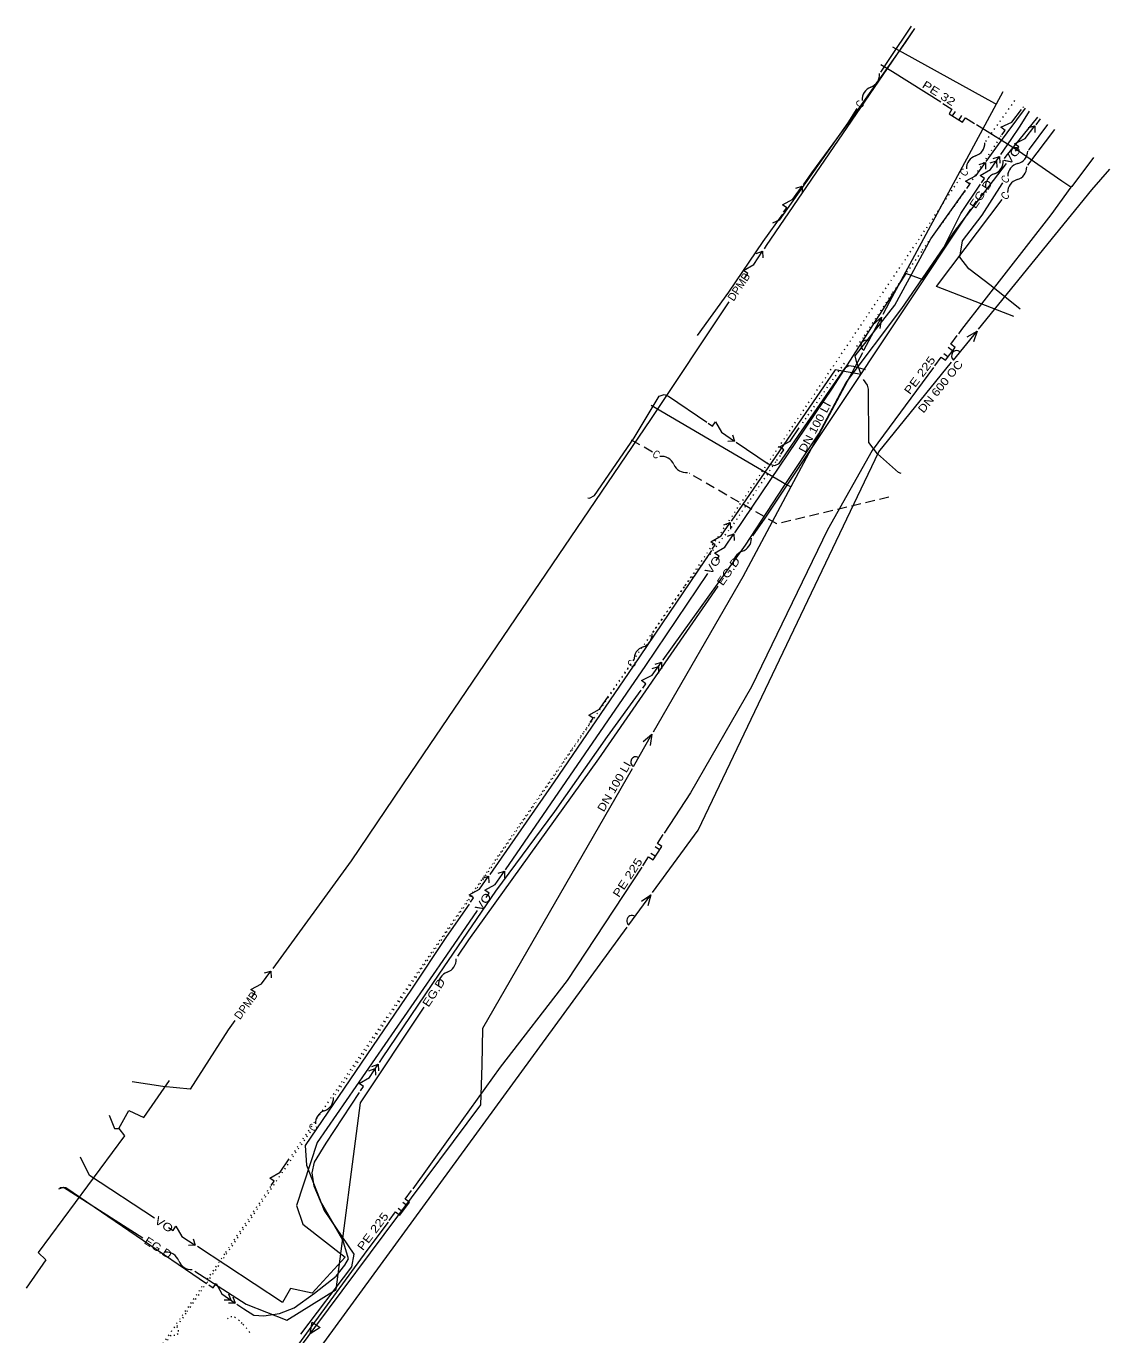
# Model space of a CAD drawing. Extents: x -601552 to -601367, y -1161450 to -1160710.
# Drawn here: x -601468.5 to -601367, y -1160833 to -1160710.4 of the extents above; entities that cross this region are included whole.
import ezdxf
from ezdxf.enums import TextEntityAlignment as Align

# ---------------------------------------------------------------- set-up
doc = ezdxf.new("R2010")
doc.units = 0
doc.header["$LTSCALE"] = 0.3
doc.linetypes.add('DOTTED', pattern=[1.5, 0.3, -1.2])
doc.linetypes.add('MEDIUM_DASHED', pattern=[4.5, 3, -1.5])
for name, color, linetype, lineweight in [('26', 7, 'Continuous', 13), ('27', 7, 'Continuous', 13), ('34', 7, 'Continuous', 13), ('42', 7, 'DOTTED', 13), ('50', 7, 'Continuous', 13), ('52', 7, 'MEDIUM_DASHED', 13), ('54', 7, 'Continuous', 13), ('56', 7, 'Continuous', 13), ('57', 7, 'Continuous', 13), ('58', 7, 'Continuous', 13), ('59', 7, 'Continuous', 13)]:
    doc.layers.add(name, color=color, linetype=linetype, lineweight=lineweight)

msp = doc.modelspace()

# ---------------------------------------------------------------- linework, layer by layer
at = {"layer": '26'}
for points in [[(-601385.292, -1160710.595), (-601399.192, -1160730.943), (-601399.401, -1160731.257)], [(-601401.2, -1160733.961), (-601400.923, -1160733.544), (-601401.339, -1160733.267), (-601400.369, -1160732.712), (-601399.538, -1160731.463)], [(-601400.127, -1160731.671), (-601399.538, -1160731.463), (-601399.503, -1160732.087)], [(-601402.706, -1160736.223), (-601410.037, -1160747.24), (-601432.493, -1160780.306), (-601438.091, -1160788.582), (-601445.445, -1160798.686)], [(-601447.373, -1160801.335), (-601447.079, -1160800.93), (-601447.483, -1160800.636), (-601446.49, -1160800.122), (-601445.608, -1160798.909)], [(-601446.205, -1160799.093), (-601445.608, -1160798.909), (-601445.599, -1160799.534)], [(-601448.989, -1160803.555), (-601449.613, -1160804.412), (-601453.173, -1160809.967), (-601455.734, -1160809.736), (-601458.599, -1160809.287)]]:
    msp.add_lwpolyline(points, dxfattribs=at)
at = {"layer": '27'}
for points in [[(-601376.856, -1160722.775), (-601376.72, -1160722.57), (-601373.744, -1160718.905)], [(-601400.438, -1160758.138), (-601399.29, -1160756.48), (-601380.021, -1160727.529)], [(-601428.088, -1160797.524), (-601427.07, -1160795.99), (-601414.89, -1160779.02), (-601403.704, -1160762.858)], [(-601452.754, -1160827.018), (-601447.92, -1160830.11), (-601444.12, -1160831.62), (-601439.51, -1160828.74), (-601437.21, -1160811.27), (-601431.256, -1160802.298)], [(-601465.494, -1160819.309), (-601465.04, -1160819.16), (-601457.614, -1160823.91)]]:
    msp.add_lwpolyline(points, dxfattribs=at)
for centre, start, end in [((-601378.23, -1160723.0339), 289.48296, 3.22275), ((-601377.3962, -1160725.3908), 109.48296, 183.22275), ((-601401.8371, -1160758.4031), 288.44283, 2.18263), ((-601401.0462, -1160760.7747), 108.44283, 182.18263), ((-601429.5006, -1160797.8441), 289.56125, 3.30105), ((-601428.6635, -1160800.1998), 109.56125, 183.30105), ((-601455.4172, -1160826.5018), 20.5269, 94.26669), ((-601453.0759, -1160825.6252), 200.5269, 274.26669)]:
    msp.add_arc(centre, 1.25, start, end, dxfattribs=at)
at = {"layer": '34', "linetype": 'DOTTED'}
for p, q in [((-601378.623, -1160721.181), (-601375.892, -1160717.355)), ((-601432.01, -1160799.46), (-601412.103, -1160770.528)), ((-601432.01, -1160799.46), (-601439.657, -1160810.632)), ((-601441.946, -1160813.975), (-601451.6, -1160828.08)), ((-601451.6, -1160828.08), (-601453.58, -1160830.97))]:
    msp.add_line(p, q, dxfattribs=at)
for points in [[(-601409.767, -1160767.132), (-601406.8, -1160762.82), (-601380.913, -1160724.466)], [(-601453.58, -1160830.97), (-601454.43, -1160832.21), (-601454.29, -1160832.57), (-601454.3, -1160832.91), (-601454.61, -1160833.07), (-601454.99, -1160833.04), (-601460.433, -1160841.306)]]:
    msp.add_lwpolyline(points, dxfattribs=at)
at = {"layer": '34'}
for centre, start, end in [((-601379.962, -1160721.344), 287.98429, 1.72409), ((-601379.1901, -1160723.7219), 107.98429, 181.72409), ((-601411.1361, -1160767.3579), 288.60035, 2.34014), ((-601410.3387, -1160769.7273), 108.60035, 182.34014), ((-601440.999, -1160810.8221), 288.73899, 2.47879), ((-601440.1959, -1160813.1896), 108.73899, 182.47879)]:
    msp.add_arc(centre, 1.25, start, end, dxfattribs=at)
at = {"layer": '42'}
msp.add_line((-601375.094, -1160717.931), (-601375.23, -1160718.11), dxfattribs=at)
at = {"layer": '42', "linetype": 'Continuous'}
for points in [[(-601377.102, -1160720.563), (-601376.799, -1160720.165), (-601377.196, -1160719.862), (-601376.192, -1160719.37), (-601375.282, -1160718.178)], [(-601397.819, -1160750.498), (-601397.535, -1160750.087), (-601397.946, -1160749.802), (-601396.966, -1160749.264), (-601396.114, -1160748.03)], [(-601415.683, -1160775.624), (-601415.399, -1160775.212), (-601415.811, -1160774.928), (-601414.831, -1160774.39), (-601413.978, -1160773.156)], [(-601445.583, -1160819.002), (-601445.302, -1160818.588), (-601445.715, -1160818.307), (-601444.738, -1160817.762), (-601443.893, -1160816.523)]]:
    msp.add_lwpolyline(points, dxfattribs=at)
at = {"layer": '42'}
for points in [[(-601377.168, -1160720.649), (-601377.314, -1160720.84), (-601380.74, -1160726.08), (-601384.658, -1160731.493), (-601387.432, -1160735.464), (-601390.127, -1160739.574), (-601390.889, -1160740.588)], [(-601391.881, -1160741.965), (-601394.18, -1160745.231), (-601396.007, -1160747.875)], [(-601397.902, -1160750.618), (-601398.315, -1160751.216), (-601402.429, -1160757.271), (-601406.922, -1160762.944), (-601413.916, -1160773.066)], [(-601415.749, -1160775.719), (-601417.505, -1160778.26), (-601427.424, -1160792.602), (-601439.982, -1160810.784), (-601443.806, -1160816.394)], [(-601445.656, -1160819.108), (-601449.96, -1160825.423), (-601456.184, -1160834.473)], [(-601449.689, -1160831.483), (-601449.368, -1160831.276), (-601449.018, -1160831.325), (-601448.621, -1160831.629), (-601448.389, -1160831.836), (-601448.228, -1160831.998), (-601447.921, -1160832.333), (-601447.638, -1160832.708), (-601447.427, -1160833.028)]]:
    msp.add_lwpolyline(points, dxfattribs=at)
at = {"layer": '50'}
for p, q in [((-601374.667, -1160723.418), (-601372.137, -1160720.065)), ((-601380.54, -1160731.2), (-601377.087, -1160726.625))]:
    msp.add_line(p, q, dxfattribs=at)
for points in [[(-601385.598, -1160710.385), (-601387.65, -1160713.4), (-601388.483, -1160714.688)], [(-601390.691, -1160718.102), (-601391.55, -1160719.43), (-601397.99, -1160728.55), (-601398.603, -1160728.852)], [(-601374.607, -1160722.004), (-601374.53, -1160721.91), (-601372.804, -1160719.583)], [(-601380.79, -1160730.51), (-601378.96, -1160728.08), (-601377.1, -1160725.17), (-601377.029, -1160725.077)], [(-601375.407, -1160736.893), (-601378.13, -1160734.72), (-601380.21, -1160733.11), (-601381.05, -1160732.04), (-601380.79, -1160730.51)], [(-601375.985, -1160737.58), (-601383.25, -1160734.79), (-601380.54, -1160731.2)]]:
    msp.add_lwpolyline(points, dxfattribs=at)
for centre, start, end in [((-601389.825, -1160714.9215), 290.23668, 3.97647), ((-601388.9602, -1160717.2671), 110.23668, 183.97647), ((-601375.9283, -1160722.045), 284.15618, 357.89598), ((-601375.3169, -1160724.4691), 104.15618, 177.89598), ((-601376.0264, -1160723.5589), 286.08984, 359.82963), ((-601375.3335, -1160725.9609), 106.08984, 179.82963)]:
    msp.add_arc(centre, 1.25, start, end, dxfattribs=at)
at = {"layer": '52'}
msp.add_line((-601409.858, -1160750.294), (-601412.056, -1160749.026), dxfattribs=at)
msp.add_lwpolyline([(-601387.692, -1160754.517), (-601398.21, -1160757.01), (-601406.406, -1160752.284)], dxfattribs=at)
at = {"layer": '52', "linetype": 'Continuous'}
for centre, start, end in [((-601409.0088, -1160751.9376), 23.16193, 96.90172), ((-601406.7103, -1160750.9543), 203.16193, 276.90172)]:
    msp.add_arc(centre, 1.25, start, end, dxfattribs=at)
at = {"layer": '54'}
for p, q in [((-601381.735, -1160718.79), (-601381.469, -1160718.367)), ((-601381.125, -1160719.174), (-601380.858, -1160718.751)), ((-601381.736, -1160740.798), (-601382.138, -1160740.5)), ((-601382.164, -1160741.377), (-601382.566, -1160741.08)), ((-601409.197, -1160787.557), (-601409.615, -1160787.283)), ((-601409.593, -1160788.16), (-601410.011, -1160787.885)), ((-601433.292, -1160821.468), (-601433.692, -1160821.168)), ((-601432.86, -1160820.89), (-601433.26, -1160820.591))]:
    msp.add_line(p, q, dxfattribs=at)
for points in [[(-601382.828, -1160717.512), (-601387.36, -1160714.66), (-601388.468, -1160714.014)], [(-601382.642, -1160717.629), (-601381.795, -1160718.162), (-601382.062, -1160718.585), (-601380.792, -1160719.384), (-601380.526, -1160718.96), (-601379.679, -1160719.493)], [(-601370.66, -1160725.48), (-601371.48, -1160724.92), (-601375.6, -1160722.06), (-601379.487, -1160719.614)], [(-601368.52, -1160722.674), (-601370.55, -1160725.4), (-601370.66, -1160725.48), (-601372.52, -1160728.07), (-601380.88, -1160738.8), (-601381.192, -1160739.222)], [(-601383.39, -1160742.194), (-601382.796, -1160741.39), (-601382.394, -1160741.688), (-601381.502, -1160740.482), (-601381.904, -1160740.184), (-601381.309, -1160739.38)], [(-601383.512, -1160742.359), (-601389.26, -1160750.13), (-601393.45, -1160757.56), (-601400.58, -1160772.28), (-601406.28, -1160782.21), (-601408.766, -1160785.992)], [(-601410.772, -1160789.043), (-601410.223, -1160788.208), (-601409.805, -1160788.482), (-601408.981, -1160787.229), (-601409.399, -1160786.954), (-601408.85, -1160786.119)], [(-601410.856, -1160789.171), (-601417.85, -1160799.81), (-601424.13, -1160807.91), (-601429.16, -1160814.92), (-601432.318, -1160819.325)], [(-601434.522, -1160822.278), (-601433.923, -1160821.477), (-601433.523, -1160821.777), (-601432.625, -1160820.575), (-601433.025, -1160820.276), (-601432.426, -1160819.475)], [(-601434.629, -1160822.427), (-601436.62, -1160825.09), (-601441.77, -1160832.15), (-601445.61, -1160837.44), (-601450.15, -1160843.5), (-601453.92, -1160848.12), (-601461.6, -1160856.34), (-601468.333, -1160866.199)]]:
    msp.add_lwpolyline(points, dxfattribs=at)
at = {"layer": '56'}
for p, q in [((-601390.054, -1160740.745), (-601388.404, -1160737.658)), ((-601381.652, -1160741.665), (-601379.442, -1160738.951)), ((-601411.648, -1160779.76), (-601409.902, -1160776.727)), ((-601412.066, -1160794.597), (-601410.001, -1160791.771)), ((-601444.537, -1160839.064), (-601412.215, -1160794.802))]:
    msp.add_line(p, q, dxfattribs=at)
for points in [[(-601377.649, -1160717.694), (-601377.785, -1160717.616), (-601387.329, -1160712.347)], [(-601377.015, -1160716.545), (-601377.649, -1160717.694), (-601387.63, -1160736.209), (-601388.272, -1160737.411)], [(-601379.31, -1160738.789), (-601368.67, -1160725.72), (-601366.995, -1160723.773)], [(-601389.206, -1160738.363), (-601388.404, -1160737.658), (-601388.545, -1160738.716)], [(-601380.364, -1160739.489), (-601379.442, -1160738.951), (-601379.783, -1160739.963)], [(-601409.852, -1160791.566), (-601405.588, -1160785.728), (-601388.65, -1160750.26), (-601381.817, -1160741.868)], [(-601390.185, -1160740.99), (-601396.887, -1160753.533), (-601401.401, -1160761.966), (-601409.787, -1160776.529)], [(-601396.887, -1160753.533), (-601397.301, -1160753.343), (-601409.988, -1160745.938)], [(-601410.726, -1160777.406), (-601409.902, -1160776.727), (-601410.076, -1160777.781)], [(-601411.759, -1160779.952), (-601425.771, -1160804.283), (-601425.855, -1160807.742), (-601425.957, -1160811.454), (-601441.536, -1160832.32)], [(-601410.894, -1160792.357), (-601410.001, -1160791.771), (-601410.288, -1160792.8)], [(-601441.536, -1160832.32), (-601447.526, -1160840.405), (-601457.885, -1160844.228)]]:
    msp.add_lwpolyline(points, dxfattribs=at)
msp.add_lwpolyline([(-601441.008, -1160832.316), (-601441.931, -1160832.898), (-601441.734, -1160831.826)], close=True, dxfattribs=at)
for centre, start, end in [((-601389.8179, -1160740.3036), 61.88239, 241.88239), ((-601381.3364, -1160741.2772), 50.84818, 230.84817), ((-601411.3988, -1160779.3266), 60.06273, 240.06273), ((-601411.7706, -1160794.1936), 53.86138, 233.86138)]:
    msp.add_arc(centre, 0.5, start, end, dxfattribs=at)
at = {"layer": '57'}
for points in [[(-601385.287, -1160710.598), (-601386.176, -1160711.912), (-601391.036, -1160718.828), (-601394.966, -1160724.138), (-601395.746, -1160725.242)], [(-601378.577, -1160723.053), (-601377.44, -1160721.47), (-601374.9, -1160718.071)], [(-601380.408, -1160725.604), (-601380.117, -1160725.198), (-601380.523, -1160724.906), (-601379.534, -1160724.386), (-601378.659, -1160723.167)], [(-601379.255, -1160723.355), (-601378.659, -1160723.167), (-601378.646, -1160723.792)], [(-601397.561, -1160727.811), (-601397.272, -1160727.403), (-601397.681, -1160727.114), (-601396.695, -1160726.586), (-601395.83, -1160725.361)], [(-601396.425, -1160725.553), (-601395.83, -1160725.361), (-601395.812, -1160725.986)], [(-601390.288, -1160743.012), (-601390.735, -1160741.809), (-601390.86, -1160741.28), (-601387.13, -1160736.51), (-601383.78, -1160730.3), (-601380.511, -1160725.748)], [(-601397.683, -1160727.984), (-601399.503, -1160730.56), (-601402.73, -1160735.301), (-601405.66, -1160739.38)], [(-601390.288, -1160743.012), (-601392.738, -1160742.572), (-601402.486, -1160756.763)], [(-601402.01, -1160749.365), (-601399.02, -1160751.4), (-601398.38, -1160751.56), (-601397.97, -1160751.36), (-601391.76, -1160742.35), (-601391.44, -1160742.19), (-601391.02, -1160742.23), (-601389.922, -1160742.537)], [(-601386.534, -1160752.291), (-601386.803, -1160752.203), (-601388.773, -1160750.459), (-601389.584, -1160749.397), (-601389.623, -1160744.397), (-601389.698, -1160744.018), (-601390.088, -1160743.491)], [(-601415.902, -1160754.583), (-601415.76, -1160754.62), (-601415.3, -1160754.36), (-601411.58, -1160748.94), (-601409.24, -1160745.06), (-601408.77, -1160744.9), (-601408.35, -1160745.05), (-601404.772, -1160747.485)], [(-601404.639, -1160747.576), (-601404.225, -1160747.857), (-601403.944, -1160747.444), (-601403.399, -1160748.42), (-601402.158, -1160749.264)], [(-601402.361, -1160748.673), (-601402.158, -1160749.264), (-601402.783, -1160749.293)], [(-601404.252, -1160759.38), (-601403.972, -1160758.965), (-601404.387, -1160758.686), (-601403.413, -1160758.136), (-601402.575, -1160756.892)], [(-601403.165, -1160757.097), (-601402.575, -1160756.892), (-601402.543, -1160757.516)], [(-601404.338, -1160759.507), (-601411.652, -1160770.355), (-601419.072, -1160781.192), (-601425.098, -1160789.856)], [(-601426.918, -1160792.472), (-601426.632, -1160792.062), (-601427.043, -1160791.776), (-601426.061, -1160791.241), (-601425.205, -1160790.009)], [(-601425.798, -1160790.206), (-601425.205, -1160790.009), (-601425.183, -1160790.634)], [(-601427.043, -1160792.653), (-601429.141, -1160795.669), (-601432.441, -1160800.597), (-601442.402, -1160815.271), (-601442.268, -1160817.109), (-601440.635, -1160821.35), (-601437.83, -1160825.438), (-601438.047, -1160826.636), (-601442.824, -1160832.943)]]:
    msp.add_lwpolyline(points, dxfattribs=at)
at = {"layer": '58'}
msp.add_line((-601373.518, -1160719.068), (-601373.935, -1160719.615), dxfattribs=at)
for points in [[(-601375.833, -1160722.099), (-601375.529, -1160721.701), (-601375.926, -1160721.398), (-601374.922, -1160720.907), (-601374.011, -1160719.715)], [(-601374.613, -1160719.885), (-601374.011, -1160719.715), (-601374.017, -1160720.34)], [(-601376.723, -1160723.264), (-601381.67, -1160729.74), (-601384.5, -1160734.14), (-601386.12, -1160733.55), (-601393.03, -1160744.29), (-601402.155, -1160757.861)], [(-601403.897, -1160760.45), (-601403.618, -1160760.035), (-601404.032, -1160759.756), (-601403.06, -1160759.205), (-601402.223, -1160757.961)], [(-601402.813, -1160758.166), (-601402.223, -1160757.961), (-601402.19, -1160758.585)], [(-601404.707, -1160761.656), (-601410.52, -1160770.3), (-601423.652, -1160789.434)], [(-601425.431, -1160792.026), (-601425.148, -1160791.614), (-601425.56, -1160791.331), (-601424.582, -1160790.789), (-601423.733, -1160789.552)], [(-601424.326, -1160789.753), (-601423.733, -1160789.552), (-601423.707, -1160790.177)], [(-601426.27, -1160793.249), (-601429.49, -1160797.94), (-601441.29, -1160814.99), (-601443.2, -1160820.87), (-601442.61, -1160822.63), (-601438.64, -1160825.72), (-601441.73, -1160829.1), (-601443.79, -1160828.66), (-601444.53, -1160829.98), (-601452.503, -1160824.728)], [(-601459.87, -1160813.65), (-601458.91, -1160811.99), (-601457.52, -1160812.62), (-601455.118, -1160809.183)], [(-601460.755, -1160812.421), (-601460.26, -1160813.66), (-601459.87, -1160813.65)], [(-601459.87, -1160813.65), (-601459.34, -1160814.35), (-601467.41, -1160825.27), (-601466.7, -1160825.98), (-601468.546, -1160828.616)], [(-601456.533, -1160822.073), (-601462.61, -1160818.07), (-601463.465, -1160816.36)], [(-601455.203, -1160822.949), (-601454.786, -1160823.224), (-601454.51, -1160822.807), (-601453.95, -1160823.774), (-601452.698, -1160824.6)], [(-601452.909, -1160824.011), (-601452.698, -1160824.6), (-601453.322, -1160824.638)]]:
    msp.add_lwpolyline(points, dxfattribs=at)
at = {"layer": '59'}
for points in [[(-601377.212, -1160722.412), (-601376.243, -1160720.991), (-601375.412, -1160719.742), (-601374.521, -1160718.344)], [(-601379.017, -1160725.063), (-601378.735, -1160724.649), (-601379.148, -1160724.368), (-601378.172, -1160723.823), (-601377.328, -1160722.583)], [(-601378.201, -1160723.199), (-601377.609, -1160722.996), (-601377.581, -1160723.621)], [(-601377.919, -1160722.785), (-601377.328, -1160722.583), (-601377.299, -1160723.207)], [(-601408.871, -1160769.79), (-601408.854, -1160769.767), (-601401.152, -1160759.008), (-601397.532, -1160753.521), (-601394.263, -1160748.57), (-601391.693, -1160743.767), (-601386.492, -1160736.826), (-601382.551, -1160731.122), (-601380.967, -1160727.927), (-601379.108, -1160725.196)], [(-601410.766, -1160772.399), (-601410.472, -1160771.995), (-601410.876, -1160771.701), (-601409.884, -1160771.186), (-601409.003, -1160769.972)], [(-601409.6, -1160770.156), (-601409.003, -1160769.972), (-601408.993, -1160770.597)], [(-601409.894, -1160770.561), (-601409.297, -1160770.376), (-601409.287, -1160771.001)], [(-601435.448, -1160807.473), (-601435.162, -1160807.04), (-601429.844, -1160799.215), (-601424.537, -1160791.435), (-601419.019, -1160783.968), (-601414.061, -1160776.937), (-601410.899, -1160772.584)], [(-601437.21, -1160810.14), (-601436.934, -1160809.722), (-601437.351, -1160809.447), (-601436.383, -1160808.888), (-601435.556, -1160807.636)], [(-601436.42, -1160808.264), (-601435.832, -1160808.054), (-601435.795, -1160808.677)], [(-601436.145, -1160807.847), (-601435.556, -1160807.636), (-601435.519, -1160808.26)], [(-601448.818, -1160830.115), (-601448.158, -1160830.566), (-601447.223, -1160831.153), (-601446.271, -1160831.207), (-601444.801, -1160830.984), (-601443.444, -1160830.472), (-601441.529, -1160829.086), (-601439.51, -1160827.502), (-601438.682, -1160826.477), (-601438.343, -1160825.883), (-601438.862, -1160824.089), (-601440.951, -1160820.462), (-601441.546, -1160819.06), (-601441.76, -1160817.807), (-601441.534, -1160816.814), (-601440.446, -1160815.038), (-601437.309, -1160810.29)], [(-601465.405, -1160819.179), (-601464.83, -1160819.179), (-601451.661, -1160828.174)], [(-601451.441, -1160828.324), (-601451.028, -1160828.606), (-601450.746, -1160828.193), (-601450.203, -1160829.17), (-601448.964, -1160830.016)], [(-601449.578, -1160829.142), (-601449.377, -1160829.734), (-601450.001, -1160829.761)], [(-601449.165, -1160829.424), (-601448.964, -1160830.016), (-601449.588, -1160830.043)]]:
    msp.add_lwpolyline(points, dxfattribs=at)

# ---------------------------------------------------------------- texts
at = {"layer": '26'}
for rotation, p in [(56.359, (-601401.4517, -1160735.0137)), (53.949, (-601447.6551, -1160802.3577))]:
    msp.add_text('DPMB', height=0.75, rotation=rotation, dxfattribs=at).set_placement(p, align=Align.CENTER)
at = {"layer": '27'}
for rotation, width, p in [(56.353, 1.2, (-601378.674, -1160726.1823)), (55.313, 1.2, (-601402.3309, -1160761.5339)), (56.431, 1.2, (-601429.9403, -1160800.9929)), (327.397, 1.15, (-601456.2386, -1160825.2334))]:
    msp.add_text('EG.D ', height=0.75, rotation=rotation, dxfattribs=dict(at, width=width)).set_placement(p, align=Align.CENTER)
at = {"layer": '34', "width": 0.8}
for rotation, p in [(54.854, (-601380.1895, -1160724.0549)), (55.47, (-601411.3336, -1160770.0723)), (55.609, (-601441.1908, -1160813.5355))]:
    msp.add_text('C', height=0.75, rotation=rotation, dxfattribs=at).set_placement(p, align=Align.RIGHT)
at = {"layer": '50', "width": 0.8}
for rotation, p in [(57.107, (-601389.9454, -1160717.6401)), (51.026, (-601376.3365, -1160724.7353)), (52.96, (-601376.343, -1160726.2612))]:
    msp.add_text('C', height=0.75, rotation=rotation, dxfattribs=at).set_placement(p, align=Align.RIGHT)
at = {"layer": '52', "width": 0.8}
msp.add_text('C', height=0.75, rotation=330.032, dxfattribs=at).set_placement((-601409.4306, -1160750.9723), align=Align.RIGHT)
at = {"layer": '54', "width": 1.25}
msp.add_text('PE 32', height=0.75, rotation=327.82, dxfattribs=at).set_placement((-601384.659, -1160716.083))
for rotation, p in [(53.512, (-601383.2872, -1160741.656)), (56.68, (-601410.743, -1160788.646)), (53.214, (-601434.5246, -1160821.8821))]:
    msp.add_text('PE 225', height=0.75, rotation=rotation, dxfattribs=at).set_placement(p, align=Align.RIGHT)
at = {"layer": '56', "width": 1.15}
for s, rotation, p in [('DN 600 OC', 50.821, (-601384.462, -1160746.699)), ('DN 100 LI', 61.765, (-601395.538, -1160750.412))]:
    msp.add_text(s, height=0.75, rotation=rotation, dxfattribs=at).set_placement(p)
msp.add_text('DN 100 LI', height=0.75, rotation=60.063, dxfattribs=at).set_placement((-601411.8271, -1160779.5643), align=Align.RIGHT)
at = {"layer": '58'}
for rotation, width, p in [(52.622, 1.3, (-601375.8258, -1160722.7087)), (56.082, 1.25, (-601403.8721, -1160761.0858)), (55.537, 1.25, (-601425.4093, -1160792.6577)), (326.626, 1.25, (-601455.8428, -1160822.9765))]:
    msp.add_text('VO', height=0.75, rotation=rotation, dxfattribs=dict(at, width=width)).set_placement(p, align=Align.CENTER)

doc.saveas('drawing.dxf')
